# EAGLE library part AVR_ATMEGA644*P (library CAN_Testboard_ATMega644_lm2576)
MICROCONTROLLER 64 kBytes FLASH 4 kBytes SRAM 2 kBytes EEPROM DUAL USART 8-channel 10 bit ADC
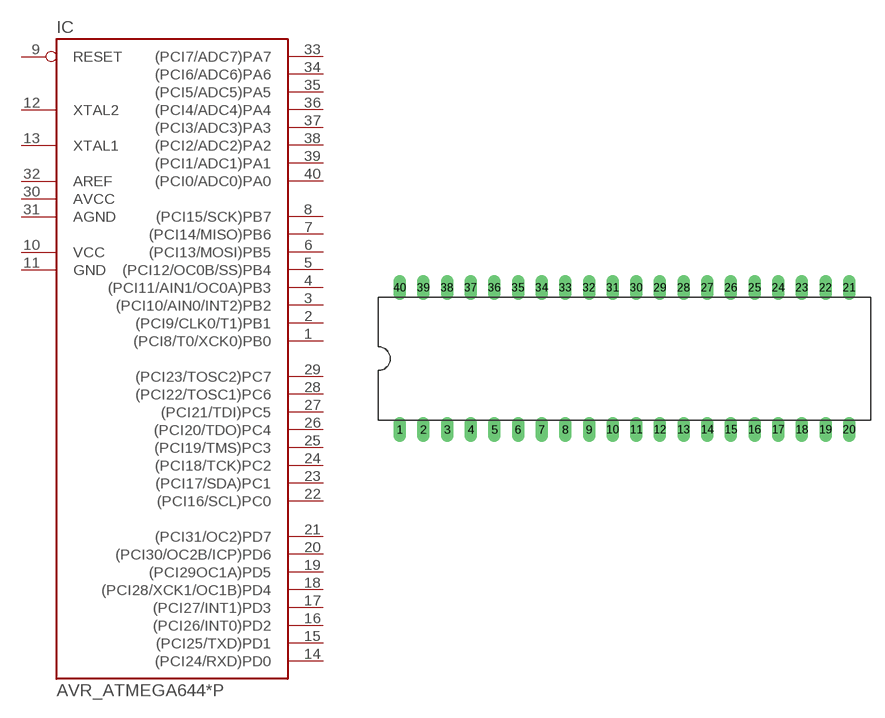
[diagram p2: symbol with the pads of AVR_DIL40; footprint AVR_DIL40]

Designator prefix IC

## AVR_ATMEGA644P, AVR_ATMEGA644-20P, AVR_ATMEGA644V-10P  [AVR_DIL40]
1  (PCI8/T0/XCK0)PB0
2  (PCI9/CLK0/T1)PB1
3  (PCI10/AIN0/INT2)PB2
4  (PCI11/AIN1/OC0A)PB3
5  (PCI12/OC0B/SS)PB4
6  (PCI13/MOSI)PB5
7  (PCI14/MISO)PB6
8  (PCI15/SCK)PB7
9  RESET  in
10  VCC  pwr
11  GND  pwr
12  XTAL2
13  XTAL1
14  (PCI24/RXD)PD0
15  (PCI25/TXD)PD1
16  (PCI26/INT0)PD2
17  (PCI27/INT1)PD3
18  (PCI28/XCK1/OC1B)PD4
19  (PCI29OC1A)PD5
20  (PCI30/OC2B/ICP)PD6
21  (PCI31/OC2)PD7
22  (PCI16/SCL)PC0
23  (PCI17/SDA)PC1
24  (PCI18/TCK)PC2
25  (PCI19/TMS)PC3
26  (PCI20/TDO)PC4
27  (PCI21/TDI)PC5
28  (PCI22/TOSC1)PC6
29  (PCI23/TOSC2)PC7
30  AVCC  pwr
31  AGND  pwr
32  AREF  pwr
33  (PCI7/ADC7)PA7
34  (PCI6/ADC6)PA6
35  (PCI5/ADC5)PA5
36  (PCI4/ADC4)PA4
37  (PCI3/ADC3)PA3
38  (PCI2/ADC2)PA2
39  (PCI1/ADC1)PA1
40  (PCI0/ADC0)PA0

## Footprint AVR_DIL40 (pad centres in mm)
Dual In Line
drill 0.813 long: 1 -24.13,-7.62; 2 -21.59,-7.62; 3 -19.05,-7.62; 4 -16.51,-7.62; 5 -13.97,-7.62; 6 -11.43,-7.62; 7 -8.89,-7.62; 8 -6.35,-7.62; 9 -3.81,-7.62; 10 -1.27,-7.62; 11 1.27,-7.62; 12 3.81,-7.62; 13 6.35,-7.62; 14 8.89,-7.62; 15 11.43,-7.62; 16 13.97,-7.62; 17 16.51,-7.62; 18 19.05,-7.62; 19 21.59,-7.62; 20 24.13,-7.62; 21 24.13,7.62; 22 21.59,7.62; 23 19.05,7.62; 24 16.51,7.62; 25 13.97,7.62; 26 11.43,7.62; 27 8.89,7.62; 28 6.35,7.62; 29 3.81,7.62; 30 1.27,7.62; 31 -1.27,7.62; 32 -3.81,7.62; 33 -6.35,7.62; 34 -8.89,7.62; 35 -11.43,7.62; 36 -13.97,7.62; 37 -16.51,7.62; 38 -19.05,7.62; 39 -21.59,7.62; 40 -24.13,7.62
